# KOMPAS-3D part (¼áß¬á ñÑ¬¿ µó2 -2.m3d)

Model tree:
1. Эскиз:1
2. Операция выдавливания:1
     Толщина стенки 1 = 7; Толщина стенки 2 = 6; Расстояние 1 = 0.6
3. Эскиз:2
4. Вырезать элемент выдавливания:1
     Толщина стенки 2 = 15; Расстояние 1 = 10
5. Эскиз:3
6. Вырезать элемент выдавливания:2
     Толщина стенки 1 = 8; Толщина стенки 2 = 15; Расстояние 1 = 10
7. Эскиз:4
8. Вырезать элемент выдавливания:3
     Толщина стенки 1 = 7; Расстояние 1 = 10
9. Эскиз:6
10. Вырезать элемент выдавливания:5
     Толщина стенки 1 = 7; Расстояние 1 = 10
